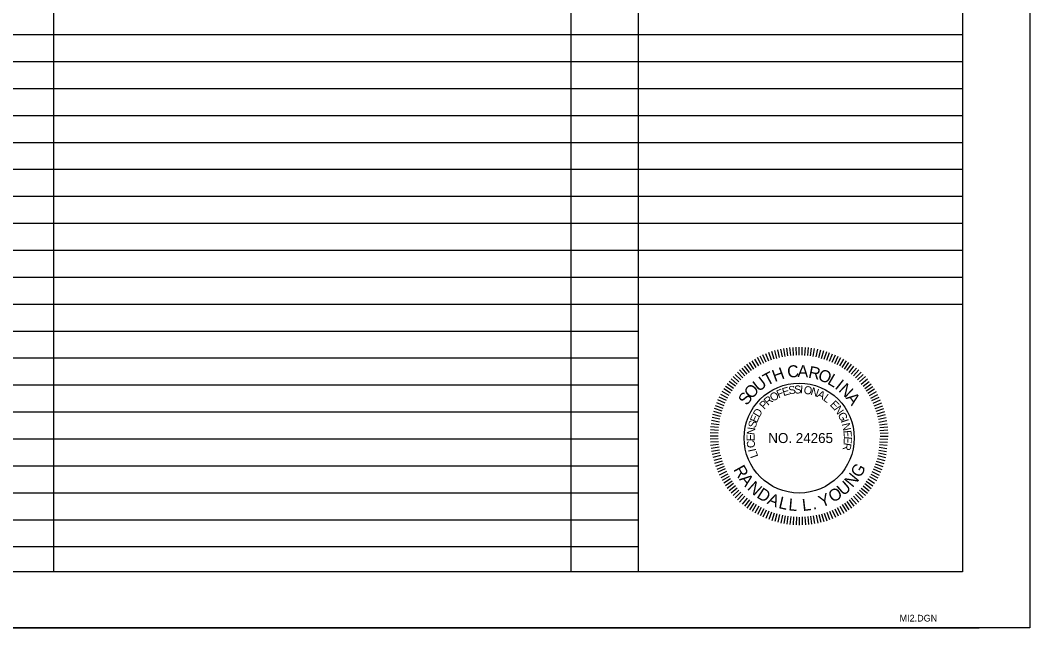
# Model space of a CAD drawing. Extents: x 8134 to 11793, y 3225 to 13425.
# Drawn here: x 11333.5 to 11782.5, y 6625 to 6895.5 of the extents above; entities that cross this region are included whole.
import ezdxf

# ---------------------------------------------------------------- set-up
doc = ezdxf.new("R2010")
doc.units = 0
for name, color, linetype in [('RD_SHT_Bndy', 7, 'Continuous'), ('RD_SHT_IplotShp', 7, 'Continuous'), ('RD_SHT_TX', 7, 'Continuous'), ('RD_TX_PEShield', 7, 'Continuous')]:
    doc.layers.add(name, color=color, linetype=linetype)

msp = doc.modelspace()

# ---------------------------------------------------------------- linework, layer by layer
at = {"layer": 'RD_SHT_Bndy'}
for p, q in [((11348.45, 6650), (11348.45, 7661)), ((11578.45, 6650), (11578.45, 7661)), ((11608.45, 6650), (11608.45, 7661)), ((11752.45, 6889), (10077.45, 6889)), ((11752.45, 6877), (10077.45, 6877)), ((11752.45, 6865), (10077.45, 6865)), ((11752.45, 6853), (10077.45, 6853)), ((11752.45, 6841), (10077.45, 6841)), ((11752.45, 6829), (10077.45, 6829)), ((11752.45, 6817), (10077.45, 6817)), ((11752.45, 6805), (10077.45, 6805)), ((11752.45, 6793), (10077.45, 6793)), ((11752.45, 6781), (10077.45, 6781)), ((11752.45, 6769), (10077.45, 6769)), ((11608.45, 6757), (10077.45, 6757)), ((11608.45, 6745), (10077.45, 6745)), ((11608.45, 6733), (10077.45, 6733)), ((11608.45, 6721), (10077.45, 6721)), ((11608.45, 6709), (10077.45, 6709)), ((11608.45, 6697), (10077.45, 6697)), ((11608.45, 6685), (10077.45, 6685)), ((11608.45, 6673), (10077.45, 6673)), ((11608.45, 6661), (10077.45, 6661)), ((10000, 6625), (11760, 6625)), ((11760, 6625), (10000, 6625))]:
    msp.add_line(p, q, dxfattribs=at)
msp.add_lwpolyline([(10077.45, 7700), (11752.45, 7700), (11752.45, 6650), (10077.45, 6650)], close=True, dxfattribs=at)
at = {"layer": 'RD_SHT_IplotShp'}
msp.add_lwpolyline([(9986.5, 7725), (11782.45, 7725), (11782.45, 6625), (9986.5, 6625)], close=True, dxfattribs=at)
at = {"layer": 'RD_TX_PEShield'}
for p, q in [((11669.98, 6744.98), (11669, 6748.4)), ((11669.98, 6744.98), (11669, 6748.4)), ((11671.19, 6745.31), (11670.33, 6748.76)), ((11671.19, 6745.31), (11670.33, 6748.76)), ((11672.41, 6745.64), (11671.67, 6749.12)), ((11672.41, 6745.64), (11671.67, 6749.12)), ((11673.65, 6745.83), (11673.03, 6749.33)), ((11673.65, 6745.83), (11673.03, 6749.33)), ((11674.89, 6746.03), (11674.4, 6749.55)), ((11674.89, 6746.03), (11674.4, 6749.55)), ((11676.13, 6746.23), (11675.76, 6749.77)), ((11676.13, 6746.23), (11675.76, 6749.77)), ((11677.39, 6746.29), (11677.14, 6749.84)), ((11677.39, 6746.29), (11677.14, 6749.84)), ((11678.65, 6746.36), (11678.52, 6749.91)), ((11678.65, 6746.36), (11678.52, 6749.91)), ((11679.9, 6746.42), (11679.9, 6749.98)), ((11679.9, 6746.42), (11679.9, 6749.98)), ((11681.16, 6746.36), (11681.28, 6749.91)), ((11681.16, 6746.36), (11681.28, 6749.91)), ((11682.41, 6746.29), (11682.66, 6749.84)), ((11682.41, 6746.29), (11682.66, 6749.84)), ((11683.67, 6746.23), (11684.04, 6749.77)), ((11683.67, 6746.23), (11684.04, 6749.77)), ((11684.91, 6746.03), (11685.41, 6749.55)), ((11684.91, 6746.03), (11685.41, 6749.55)), ((11686.15, 6745.83), (11686.77, 6749.33)), ((11686.15, 6745.83), (11686.77, 6749.33)), ((11687.4, 6745.64), (11688.14, 6749.12)), ((11687.4, 6745.64), (11688.14, 6749.12)), ((11687.4, 6745.64), (11688.14, 6749.12)), ((11688.61, 6745.31), (11689.47, 6748.76)), ((11688.61, 6745.31), (11689.47, 6748.76)), ((11688.61, 6745.31), (11689.47, 6748.76)), ((11689.83, 6744.98), (11690.81, 6748.4)), ((11689.83, 6744.98), (11690.81, 6748.4)), ((11689.83, 6744.98), (11690.81, 6748.4)), ((11660.82, 6740.91), (11658.94, 6743.92)), ((11660.82, 6740.91), (11658.94, 6743.92)), ((11661.88, 6741.59), (11660.1, 6744.68)), ((11661.88, 6741.59), (11660.1, 6744.68)), ((11663, 6742.17), (11661.33, 6745.3)), ((11663, 6742.17), (11661.33, 6745.3)), ((11664.12, 6742.74), (11662.56, 6745.93)), ((11664.12, 6742.74), (11662.56, 6745.93)), ((11665.24, 6743.31), (11663.79, 6746.56)), ((11665.24, 6743.31), (11663.79, 6746.56)), ((11666.42, 6743.76), (11665.08, 6747.05)), ((11666.42, 6743.76), (11665.08, 6747.05)), ((11667.59, 6744.21), (11666.37, 6747.55)), ((11667.59, 6744.21), (11666.37, 6747.55)), ((11668.76, 6744.66), (11667.66, 6748.04)), ((11668.76, 6744.66), (11667.66, 6748.04)), ((11691.04, 6744.66), (11692.14, 6748.04)), ((11691.04, 6744.66), (11692.14, 6748.04)), ((11691.04, 6744.66), (11692.14, 6748.04)), ((11692.21, 6744.21), (11693.43, 6747.55)), ((11692.21, 6744.21), (11693.43, 6747.55)), ((11692.21, 6744.21), (11693.43, 6747.55)), ((11693.39, 6743.76), (11694.72, 6747.05)), ((11693.39, 6743.76), (11694.72, 6747.05)), ((11693.39, 6743.76), (11694.72, 6747.05)), ((11694.56, 6743.31), (11696.01, 6746.56)), ((11694.56, 6743.31), (11696.01, 6746.56)), ((11694.56, 6743.31), (11696.01, 6746.56)), ((11695.68, 6742.74), (11697.24, 6745.93)), ((11695.68, 6742.74), (11697.24, 6745.93)), ((11695.68, 6742.74), (11697.24, 6745.93)), ((11696.8, 6742.17), (11698.47, 6745.3)), ((11696.8, 6742.17), (11698.47, 6745.3)), ((11696.8, 6742.17), (11698.47, 6745.3)), ((11697.92, 6741.59), (11699.7, 6744.68)), ((11697.92, 6741.59), (11699.7, 6744.68)), ((11697.92, 6741.59), (11699.7, 6744.68)), ((11698.98, 6740.91), (11700.86, 6743.92)), ((11698.98, 6740.91), (11700.86, 6743.92)), ((11698.98, 6740.91), (11700.86, 6743.92)), ((11655.78, 6737.16), (11653.4, 6739.81)), ((11655.78, 6737.16), (11653.4, 6739.81)), ((11656.76, 6737.96), (11654.48, 6740.68)), ((11656.76, 6737.96), (11654.48, 6740.68)), ((11657.74, 6738.75), (11655.55, 6741.55)), ((11657.74, 6738.75), (11655.55, 6741.55)), ((11658.72, 6739.54), (11656.62, 6742.42)), ((11658.72, 6739.54), (11656.62, 6742.42)), ((11659.77, 6740.22), (11657.78, 6743.17)), ((11659.77, 6740.22), (11657.78, 6743.17)), ((11700.03, 6740.22), (11702.02, 6743.17)), ((11700.03, 6740.22), (11702.02, 6743.17)), ((11700.03, 6740.22), (11702.02, 6743.17)), ((11701.09, 6739.54), (11703.18, 6742.42)), ((11701.09, 6739.54), (11703.18, 6742.42)), ((11701.09, 6739.54), (11703.18, 6742.42)), ((11702.07, 6738.75), (11704.26, 6741.55)), ((11702.07, 6738.75), (11704.26, 6741.55)), ((11702.07, 6738.75), (11704.26, 6741.55)), ((11703.04, 6737.96), (11705.33, 6740.68)), ((11703.04, 6737.96), (11705.33, 6740.68)), ((11703.04, 6737.96), (11705.33, 6740.68)), ((11704.02, 6737.16), (11706.4, 6739.81)), ((11704.02, 6737.16), (11706.4, 6739.81)), ((11704.02, 6737.16), (11706.4, 6739.81)), ((11652.32, 6733.52), (11649.6, 6735.8)), ((11652.32, 6733.52), (11649.6, 6735.8)), ((11653.12, 6734.5), (11650.47, 6736.88)), ((11653.12, 6734.5), (11650.47, 6736.88)), ((11654, 6735.39), (11651.45, 6737.86)), ((11654, 6735.39), (11651.45, 6737.86)), ((11654.89, 6736.28), (11652.42, 6738.83)), ((11654.89, 6736.28), (11652.42, 6738.83)), ((11704.91, 6736.28), (11707.38, 6738.83)), ((11704.91, 6736.28), (11707.38, 6738.83)), ((11704.91, 6736.28), (11707.38, 6738.83)), ((11705.8, 6735.39), (11708.36, 6737.86)), ((11705.8, 6735.39), (11708.36, 6737.86)), ((11705.8, 6735.39), (11708.36, 6737.86)), ((11706.69, 6734.5), (11709.33, 6736.88)), ((11706.69, 6734.5), (11709.33, 6736.88)), ((11706.69, 6734.5), (11709.33, 6736.88)), ((11707.48, 6733.52), (11710.2, 6735.8)), ((11707.48, 6733.52), (11710.2, 6735.8)), ((11707.48, 6733.52), (11710.2, 6735.8)), ((11649.37, 6729.46), (11646.36, 6731.34)), ((11649.37, 6729.46), (11646.36, 6731.34)), ((11650.06, 6730.51), (11647.11, 6732.5)), ((11650.06, 6730.51), (11647.11, 6732.5)), ((11650.74, 6731.56), (11647.86, 6733.66)), ((11650.74, 6731.56), (11647.86, 6733.66)), ((11651.53, 6732.54), (11648.73, 6734.73)), ((11651.53, 6732.54), (11648.73, 6734.73)), ((11708.27, 6732.54), (11711.07, 6734.73)), ((11708.27, 6732.54), (11711.07, 6734.73)), ((11708.27, 6732.54), (11711.07, 6734.73)), ((11709.06, 6731.56), (11711.94, 6733.66)), ((11709.06, 6731.56), (11711.94, 6733.66)), ((11709.06, 6731.56), (11711.94, 6733.66)), ((11709.75, 6730.51), (11712.7, 6732.5)), ((11709.75, 6730.51), (11712.7, 6732.5)), ((11709.75, 6730.51), (11712.7, 6732.5)), ((11710.43, 6729.46), (11713.45, 6731.34)), ((11710.43, 6729.46), (11713.45, 6731.34)), ((11710.43, 6729.46), (11713.45, 6731.34)), ((11646.97, 6725.04), (11643.72, 6726.49)), ((11646.97, 6725.04), (11643.72, 6726.49)), ((11647.54, 6726.16), (11644.35, 6727.72)), ((11647.54, 6726.16), (11644.35, 6727.72)), ((11648.11, 6727.28), (11644.98, 6728.95)), ((11648.11, 6727.28), (11644.98, 6728.95)), ((11648.69, 6728.4), (11645.6, 6730.18)), ((11648.69, 6728.4), (11645.6, 6730.18)), ((11711.12, 6728.4), (11714.2, 6730.18)), ((11711.12, 6728.4), (11714.2, 6730.18)), ((11711.12, 6728.4), (11714.2, 6730.18)), ((11711.69, 6727.28), (11714.83, 6728.95)), ((11711.69, 6727.28), (11714.83, 6728.95)), ((11711.69, 6727.28), (11714.83, 6728.95)), ((11712.26, 6726.16), (11715.46, 6727.72)), ((11712.26, 6726.16), (11715.46, 6727.72)), ((11712.26, 6726.16), (11715.46, 6727.72)), ((11712.83, 6725.04), (11716.08, 6726.49)), ((11712.83, 6725.04), (11716.08, 6726.49)), ((11712.83, 6725.04), (11716.08, 6726.49)), ((11645.62, 6721.52), (11642.24, 6722.62)), ((11645.62, 6721.52), (11642.24, 6722.62)), ((11646.07, 6722.69), (11642.73, 6723.91)), ((11646.07, 6722.69), (11642.73, 6723.91)), ((11646.52, 6723.86), (11643.23, 6725.2)), ((11646.52, 6723.86), (11643.23, 6725.2)), ((11713.28, 6723.86), (11716.58, 6725.2)), ((11713.28, 6723.86), (11716.58, 6725.2)), ((11713.28, 6723.86), (11716.58, 6725.2)), ((11713.73, 6722.69), (11717.07, 6723.91)), ((11713.73, 6722.69), (11717.07, 6723.91)), ((11713.73, 6722.69), (11717.07, 6723.91)), ((11714.18, 6721.52), (11717.57, 6722.62)), ((11714.18, 6721.52), (11717.57, 6722.62)), ((11714.18, 6721.52), (11717.57, 6722.62)), ((11644.45, 6716.63), (11640.95, 6717.25)), ((11644.45, 6716.63), (11640.95, 6717.25)), ((11644.64, 6717.87), (11641.16, 6718.61)), ((11644.64, 6717.87), (11641.16, 6718.61)), ((11644.97, 6719.09), (11641.52, 6719.95)), ((11644.97, 6719.09), (11641.52, 6719.95)), ((11645.3, 6720.3), (11641.88, 6721.28)), ((11645.3, 6720.3), (11641.88, 6721.28)), ((11714.51, 6720.3), (11717.93, 6721.28)), ((11714.51, 6720.3), (11717.93, 6721.28)), ((11714.51, 6720.3), (11717.93, 6721.28)), ((11714.83, 6719.09), (11718.28, 6719.95)), ((11714.83, 6719.09), (11718.28, 6719.95)), ((11714.83, 6719.09), (11718.28, 6719.95)), ((11715.16, 6717.87), (11718.64, 6718.61)), ((11715.16, 6717.87), (11718.64, 6718.61)), ((11715.16, 6717.87), (11718.64, 6718.61)), ((11715.36, 6716.63), (11718.86, 6717.25)), ((11715.36, 6716.63), (11718.86, 6717.25)), ((11715.36, 6716.63), (11718.86, 6717.25)), ((11643.99, 6712.89), (11640.44, 6713.14)), ((11643.99, 6712.89), (11640.44, 6713.14)), ((11644.05, 6714.15), (11640.51, 6714.52)), ((11644.05, 6714.15), (11640.51, 6714.52)), ((11644.25, 6715.39), (11640.73, 6715.88)), ((11644.25, 6715.39), (11640.73, 6715.88)), ((11715.55, 6715.39), (11719.07, 6715.88)), ((11715.55, 6715.39), (11719.07, 6715.88)), ((11715.55, 6715.39), (11719.07, 6715.88)), ((11715.75, 6714.15), (11719.29, 6714.52)), ((11715.75, 6714.15), (11719.29, 6714.52)), ((11715.75, 6714.15), (11719.29, 6714.52)), ((11715.82, 6712.89), (11719.36, 6713.14)), ((11715.82, 6712.89), (11719.36, 6713.14)), ((11715.82, 6712.89), (11719.36, 6713.14)), ((11643.86, 6710.38), (11640.3, 6710.38)), ((11643.86, 6710.38), (11640.3, 6710.38)), ((11643.92, 6711.63), (11640.37, 6711.76)), ((11643.92, 6711.63), (11640.37, 6711.76)), ((11643.92, 6709.12), (11640.37, 6709)), ((11643.92, 6709.12), (11640.37, 6709)), ((11715.68, 6707.88), (11719.22, 6707.63)), ((11715.68, 6707.88), (11719.22, 6707.63)), ((11715.81, 6709.12), (11719.36, 6709)), ((11715.81, 6709.12), (11719.36, 6709)), ((11715.88, 6711.63), (11719.43, 6711.76)), ((11715.88, 6711.63), (11719.43, 6711.76)), ((11715.88, 6711.63), (11719.43, 6711.76)), ((11715.95, 6710.38), (11719.51, 6710.38)), ((11715.95, 6710.38), (11719.51, 6710.38)), ((11715.95, 6710.38), (11719.51, 6710.38)), ((11643.99, 6707.87), (11640.44, 6707.62)), ((11643.99, 6707.87), (11640.44, 6707.62)), ((11644.05, 6706.61), (11640.51, 6706.24)), ((11644.05, 6706.61), (11640.51, 6706.24)), ((11644.25, 6705.37), (11640.73, 6704.87)), ((11644.25, 6705.37), (11640.73, 6704.87)), ((11644.45, 6704.13), (11640.95, 6703.51)), ((11644.45, 6704.13), (11640.95, 6703.51)), ((11715.29, 6704.14), (11718.79, 6703.52)), ((11715.29, 6704.14), (11718.79, 6703.52)), ((11715.42, 6705.39), (11718.93, 6704.89)), ((11715.42, 6705.39), (11718.93, 6704.89)), ((11715.55, 6706.63), (11719.07, 6706.26)), ((11715.55, 6706.63), (11719.07, 6706.26)), ((11644.64, 6702.88), (11641.16, 6702.14)), ((11644.64, 6702.88), (11641.16, 6702.14)), ((11644.97, 6701.67), (11641.52, 6700.81)), ((11644.97, 6701.67), (11641.52, 6700.81)), ((11645.3, 6700.45), (11641.88, 6699.47)), ((11645.3, 6700.45), (11641.88, 6699.47)), ((11645.62, 6699.24), (11642.24, 6698.14)), ((11714.18, 6699.24), (11717.57, 6698.14)), ((11714.18, 6699.24), (11717.57, 6698.14)), ((11714.51, 6700.45), (11717.93, 6699.47)), ((11714.51, 6700.45), (11717.93, 6699.47)), ((11714.83, 6701.67), (11718.28, 6700.81)), ((11714.83, 6701.67), (11718.28, 6700.81)), ((11715.16, 6702.88), (11718.64, 6702.14)), ((11715.16, 6702.88), (11718.64, 6702.14)), ((11646.07, 6698.06), (11642.73, 6696.85)), ((11646.07, 6698.06), (11642.73, 6696.85)), ((11646.52, 6696.89), (11643.23, 6695.56)), ((11646.52, 6696.89), (11643.23, 6695.56)), ((11646.97, 6695.72), (11643.72, 6694.27)), ((11646.97, 6695.72), (11643.72, 6694.27)), ((11647.54, 6694.6), (11644.35, 6693.04)), ((11647.54, 6694.6), (11644.35, 6693.04)), ((11712.26, 6694.6), (11715.46, 6693.04)), ((11712.26, 6694.6), (11715.46, 6693.04)), ((11712.83, 6695.72), (11716.08, 6694.27)), ((11712.83, 6695.72), (11716.08, 6694.27)), ((11713.28, 6696.89), (11716.58, 6695.56)), ((11713.28, 6696.89), (11716.58, 6695.56)), ((11713.73, 6698.06), (11717.07, 6696.85)), ((11713.73, 6698.06), (11717.07, 6696.85)), ((11648.11, 6693.48), (11644.98, 6691.81)), ((11648.11, 6693.48), (11644.98, 6691.81)), ((11648.69, 6692.36), (11645.6, 6690.58)), ((11648.69, 6692.36), (11645.6, 6690.58)), ((11649.37, 6691.3), (11646.36, 6689.42)), ((11649.37, 6691.3), (11646.36, 6689.42)), ((11650.06, 6690.25), (11647.11, 6688.26)), ((11650.06, 6690.25), (11647.11, 6688.26)), ((11709.75, 6690.25), (11712.7, 6688.26)), ((11709.75, 6690.25), (11712.7, 6688.26)), ((11710.43, 6691.3), (11713.45, 6689.42)), ((11710.43, 6691.3), (11713.45, 6689.42)), ((11711.12, 6692.36), (11714.2, 6690.58)), ((11711.12, 6692.36), (11714.2, 6690.58)), ((11711.69, 6693.48), (11714.83, 6691.81)), ((11711.69, 6693.48), (11714.83, 6691.81)), ((11650.74, 6689.19), (11647.86, 6687.1)), ((11650.74, 6689.19), (11647.86, 6687.1)), ((11651.53, 6688.21), (11648.73, 6686.02)), ((11651.53, 6688.21), (11648.73, 6686.02)), ((11652.32, 6687.24), (11649.6, 6684.95)), ((11652.32, 6687.24), (11649.6, 6684.95)), ((11653.12, 6686.26), (11650.47, 6683.88)), ((11653.12, 6686.26), (11650.47, 6683.88)), ((11706.69, 6686.26), (11709.33, 6683.88)), ((11706.69, 6686.26), (11709.33, 6683.88)), ((11707.48, 6687.24), (11710.2, 6684.95)), ((11707.48, 6687.24), (11710.2, 6684.95)), ((11708.27, 6688.21), (11711.07, 6686.02)), ((11708.27, 6688.21), (11711.07, 6686.02)), ((11709.06, 6689.19), (11711.94, 6687.1)), ((11709.06, 6689.19), (11711.94, 6687.1)), ((11654, 6685.37), (11651.45, 6682.9)), ((11654, 6685.37), (11651.45, 6682.9)), ((11654.89, 6684.48), (11652.42, 6681.92)), ((11654.89, 6684.48), (11652.42, 6681.92)), ((11655.78, 6683.59), (11653.4, 6680.95)), ((11655.78, 6683.59), (11653.4, 6680.95)), ((11656.76, 6682.8), (11654.48, 6680.08)), ((11656.76, 6682.8), (11654.48, 6680.08)), ((11657.74, 6682.01), (11655.55, 6679.21)), ((11657.74, 6682.01), (11655.55, 6679.21)), ((11658.72, 6681.22), (11656.62, 6678.34)), ((11658.72, 6681.22), (11656.62, 6678.34)), ((11701.09, 6681.22), (11703.18, 6678.34)), ((11701.09, 6681.22), (11703.18, 6678.34)), ((11702.07, 6682.01), (11704.26, 6679.21)), ((11702.07, 6682.01), (11704.26, 6679.21)), ((11703.04, 6682.8), (11705.33, 6680.08)), ((11703.04, 6682.8), (11705.33, 6680.08)), ((11704.02, 6683.59), (11706.4, 6680.95)), ((11704.91, 6684.48), (11707.38, 6681.92)), ((11704.91, 6684.48), (11707.38, 6681.92)), ((11705.8, 6685.37), (11708.36, 6682.9)), ((11705.8, 6685.37), (11708.36, 6682.9)), ((11659.77, 6680.53), (11657.78, 6677.58)), ((11659.77, 6680.53), (11657.78, 6677.58)), ((11660.82, 6679.85), (11658.94, 6676.83)), ((11660.82, 6679.85), (11658.94, 6676.83)), ((11661.88, 6679.16), (11660.1, 6676.08)), ((11661.88, 6679.16), (11660.1, 6676.08)), ((11663, 6678.59), (11661.33, 6675.45)), ((11663, 6678.59), (11661.33, 6675.45)), ((11664.12, 6678.02), (11662.56, 6674.82)), ((11664.12, 6678.02), (11662.56, 6674.82)), ((11665.24, 6677.45), (11663.79, 6674.2)), ((11665.24, 6677.45), (11663.79, 6674.2)), ((11666.42, 6677), (11665.08, 6673.7)), ((11666.42, 6677), (11665.08, 6673.7)), ((11667.59, 6676.55), (11666.37, 6673.21)), ((11667.59, 6676.55), (11666.37, 6673.21)), ((11692.21, 6676.55), (11693.43, 6673.21)), ((11692.21, 6676.55), (11693.43, 6673.21)), ((11693.39, 6677), (11694.72, 6673.7)), ((11693.39, 6677), (11694.72, 6673.7)), ((11694.56, 6677.45), (11696.01, 6674.2)), ((11694.56, 6677.45), (11696.01, 6674.2)), ((11695.68, 6678.02), (11697.24, 6674.82)), ((11695.68, 6678.02), (11697.24, 6674.82)), ((11696.8, 6678.59), (11698.47, 6675.45)), ((11696.8, 6678.59), (11698.47, 6675.45)), ((11697.92, 6679.16), (11699.7, 6676.08)), ((11697.92, 6679.16), (11699.7, 6676.08)), ((11698.98, 6679.85), (11700.86, 6676.83)), ((11698.98, 6679.85), (11700.86, 6676.83)), ((11700.03, 6680.53), (11702.02, 6677.58)), ((11700.03, 6680.53), (11702.02, 6677.58)), ((11668.76, 6676.1), (11667.66, 6672.71)), ((11668.76, 6676.1), (11667.66, 6672.71)), ((11669.98, 6675.77), (11669, 6672.35)), ((11669.98, 6675.77), (11669, 6672.35)), ((11671.19, 6675.45), (11670.33, 6672)), ((11671.19, 6675.45), (11670.33, 6672)), ((11672.41, 6675.12), (11671.67, 6671.64)), ((11672.41, 6675.12), (11671.67, 6671.64)), ((11673.65, 6674.92), (11673.03, 6671.42)), ((11673.65, 6674.92), (11673.03, 6671.42)), ((11674.89, 6674.73), (11674.4, 6671.21)), ((11674.89, 6674.73), (11674.4, 6671.21)), ((11676.13, 6674.53), (11675.76, 6670.99)), ((11676.13, 6674.53), (11675.76, 6670.99)), ((11677.39, 6674.46), (11677.14, 6670.92)), ((11677.39, 6674.46), (11677.14, 6670.92)), ((11678.65, 6674.4), (11678.52, 6670.85)), ((11678.65, 6674.4), (11678.52, 6670.85)), ((11679.9, 6674.33), (11679.9, 6670.77)), ((11679.9, 6674.33), (11679.9, 6670.77)), ((11681.16, 6674.4), (11681.28, 6670.85)), ((11681.16, 6674.4), (11681.28, 6670.85)), ((11682.41, 6674.46), (11682.66, 6670.92)), ((11682.41, 6674.46), (11682.66, 6670.92)), ((11683.67, 6674.53), (11684.04, 6670.99)), ((11683.67, 6674.53), (11684.04, 6670.99)), ((11684.91, 6674.73), (11685.41, 6671.21)), ((11684.91, 6674.73), (11685.41, 6671.21)), ((11686.15, 6674.92), (11686.77, 6671.42)), ((11686.15, 6674.92), (11686.77, 6671.42)), ((11687.4, 6675.12), (11688.14, 6671.64)), ((11687.4, 6675.12), (11688.14, 6671.64)), ((11688.61, 6675.45), (11689.47, 6672)), ((11688.61, 6675.45), (11689.47, 6672)), ((11689.83, 6675.77), (11690.81, 6672.35)), ((11689.83, 6675.77), (11690.81, 6672.35)), ((11691.04, 6676.1), (11692.14, 6672.71)), ((11691.04, 6676.1), (11692.14, 6672.71))]:
    msp.add_line(p, q, dxfattribs=at)
msp.add_circle((11679.9, 6709.5), 24.48, dxfattribs=at)

# ---------------------------------------------------------------- texts
at = {"layer": 'RD_SHT_TX'}
msp.add_text('MI2.DGN', height=3, dxfattribs=at).set_placement((11724.55, 6627.8))
at = {"layer": 'RD_TX_PEShield'}
for s, height, rotation, p in [('T', 5.34, 28.0947, (11665.56, 6732.62)), ('H', 5.34, 19.9102, (11669, 6734.42)), ('C', 5.34, 6.8832, (11674.9, 6736.24)), ('A', 5.34, 357.9448, (11679.11, 6736.69)), ('R', 5.34, 348.267, (11683.69, 6736.44)), ('O', 5.34, 339.3286, (11687.83, 6735.52)), ('U', 5.34, 37.7726, (11661.88, 6729.88)), ('L', 5.34, 329.6507, (11692.09, 6733.82)), ('I', 5.34, 321.4663, (11695.43, 6731.83)), ('O', 5.34, 47.4504, (11658.71, 6726.56)), ('F', 3.56, 23.0853, (11670.71, 6727.16)), ('E', 3.56, 16.1843, (11672.9, 6728.13)), ('S', 3.56, 8.6909, (11675.39, 6728.89)), ('S', 3.56, 1.79, (11677.75, 6729.29)), ('I', 3.56, 354.889, (11680.15, 6729.4)), ('O', 3.56, 350.4045, (11681.7, 6729.32)), ('N', 3.56, 341.7029, (11684.68, 6728.82)), ('A', 3.56, 333.0013, (11687.55, 6727.88)), ('N', 5.34, 317.0007, (11697.12, 6730.56)), ('S', 5.34, 54.9027, (11656.68, 6723.66)), ('P', 3.56, 46.7912, (11664.39, 6721.97)), ('R', 3.56, 39.8902, (11666, 6723.75)), ('O', 3.56, 31.7869, (11668.15, 6725.56)), ('L', 3.56, 324.2997, (11690.24, 6726.51)), ('E', 3.56, 313.2251, (11693.32, 6724.21)), ('A', 5.34, 307.3229, (11700.42, 6727.36)), ('D', 3.56, 59.074, (11662.09, 6718.39)), ('N', 3.56, 305.7317, (11695.12, 6722.33)), ('S', 3.56, 73.4683, (11660.44, 6713.68)), ('E', 3.56, 66.5674, (11661.08, 6715.99)), ('G', 3.56, 297.0301, (11696.89, 6719.88)), ('I', 3.56, 288.3285, (11698.26, 6717.19)), ('N', 3.56, 82.17, (11660.03, 6710.69)), ('N', 3.56, 283.8441, (11698.81, 6715.74)), ('E', 3.56, 275.1424, (11699.53, 6712.8)), ('E', 3.56, 89.6633, (11660.05, 6708.09)), ('C', 3.56, 97.7667, (11660.44, 6705.3)), ('E', 3.56, 267.6491, (11699.79, 6710.22)), ('I', 3.56, 102.2511, (11660.83, 6703.79)), ('L', 3.56, 109.7445, (11661.74, 6701.35)), ('R', 3.56, 260.1557, (11699.72, 6707.61)), ('R', 5.34, 299.1493, (11650.5, 6695.53)), ('G', 5.34, 60.1113, (11707.01, 6691.48)), ('A', 5.34, 308.0877, (11653.03, 6691.13)), ('N', 5.34, 317.7655, (11656.5, 6686.87)), ('U', 5.34, 40.7556, (11699.51, 6683.51)), ('N', 5.34, 50.4335, (11703.6, 6687.18)), ('D', 5.34, 327.4433, (11660.64, 6683.26)), ('O', 5.34, 31.0778, (11694.86, 6680.58)), ('A', 5.34, 337.1212, (11665.32, 6680.39)), ('L', 5.34, 346.799, (11670.42, 6678.36)), ('L', 5.34, 354.9835, (11674.95, 6677.32)), ('L', 5.34, 6.5171, (11681.49, 6676.98)), ('Y', 5.34, 21.4, (11689.78, 6678.48)), ('.', 5.34, 14.7016, (11686.1, 6677.54))]:
    msp.add_text(s, height=height, rotation=rotation, dxfattribs=at).set_placement(p)
msp.add_text('NO. 24265', height=4.45, dxfattribs=at).set_placement((11666.15, 6707.27))

doc.saveas('drawing.dxf')
